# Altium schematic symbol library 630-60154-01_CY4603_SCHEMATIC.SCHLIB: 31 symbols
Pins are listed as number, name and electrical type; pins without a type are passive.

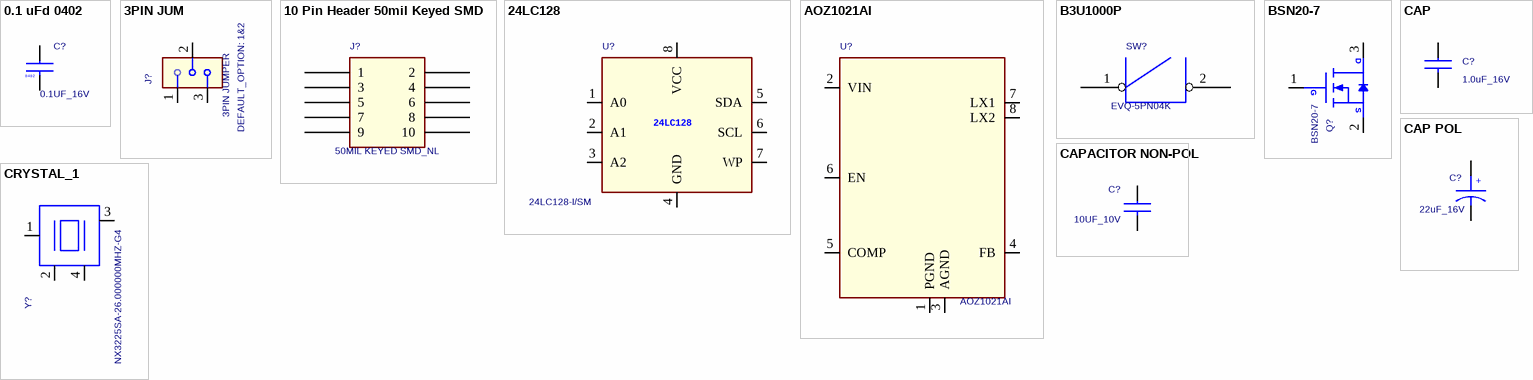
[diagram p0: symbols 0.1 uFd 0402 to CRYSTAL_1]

## 0.1 uFd 0402
designator C?, comment 0.1UF_16V
CAP .1UF 16V CERAMIC Y5V 0402; Cy_part#: 730R-10010; Manufacturer: Panasonic - ECG; Part Number: ECJ-0EF1C104Z; DEVICE: 0p1uFd_0402; CLASS: DISCRETE; ALT_SYMBOLS: C-CC0402_A
footprint CAPC1005X55M (Footprint not found)
footprint CC0402
pins: 1, 2

## 3PIN JUM
designator J?, comment 3PIN JUMPER  DEFAULT_OPTION: 1&2
CONN HEADER VERT 3POS .100 TIN; Part Number: 3-644456-3; Manufacturer: Tyco Electronics
footprint TE_3-644456-3 (Footprint not found)
pins: 1, 2, 3

## 10 Pin Header 50mil Keyed SMD
designator J?, comment 50MIL KEYED SMD_NL
CONN HEADER 10 PIN 50MIL KEYED SMD; Part Number: FTSH-105-01-L-DV-K; Manufacturer: Samtec; Cy_part#: 420R-14312; CLASS: IO; Last Edit By: SNF; DEVICE: HDR5x2x50KS
footprint SAMTEC_FTSH-105-01-L-DV-K (Footprint not found)
footprint ftsh-105-xx-x-dv-k
pins: 1, 2, 3, 4, 5, 6, 7, 8, 9, 10

## 24LC128
designator U?, comment 24LC128-I/SM
IC EEPROM 128KBIT 400KHZ 8SOIC; Manufacturer: Microchip Technology
footprint SOIC127P790X203-8M (Footprint not found)
footprint 8SOIC
pins: 1 A0, 2 A1, 3 A2, 4 GND, 5 SDA, 6 SCL, 7 WP, 8 VCC

## AOZ1021AI
designator U?
IC REG BUCK SYNC ADJ 3A 8SOIC; Manufacturer: Alpha & Omega Semiconductor Inc
footprint SOIC127P600X175-8M (Footprint not found)
footprint AOZ1021AI
pins: 1 PGND, 2 VIN, 3 AGND, 4 FB, 5 COMP, 6 EN, 7 LX1, 8 LX2

## B3U1000P
designator SW?, comment EVQ-5PN04K
footprint SW_EVQ-5PN04K (Footprint not found)
pins: 1, 2

## BSN20-7
designator Q?
MOSFET N-CH 50V 500MA SOT23; Manufacturer: Diodes Inc; PSpiceTemplate: X^@REFDES %D %G %S @MODEL
footprint SOT92P240X110-3M (Footprint not found)
pins: 1 G, 2 S, 3 D

## CAP
designator C?, comment 1.0uF_16V
CAP - CER, 1uF, 10V, +/-10%, X5R, 0402; Part Class: CAPACITORS; Num Pins: 2; Item Num: P03-15479R
footprint CAPC1608X90M (Footprint not found)
pins: 1, 2

## CAP POL
designator C?, comment 22uF_16V
CAP TANT 22UF 16V 10% 1206; Manufacturer: Nichicon; Part Number: F951C226KQAAQ2
footprint CAPCP3216X100M (Footprint not found)
pins: 1, 2

## CAPACITOR NON-POL
designator C?, comment 10UF_10V
footprint CAPC2012X145M (Footprint not found)
pins: 1, 2

## CRYSTAL_1
designator Y?, comment NX3225SA-26.000000MHZ-G4
Manufacturer: NDK
footprint OSCCC250X320X70-4M (Footprint not found)
pins: 1, 2, 3, 4

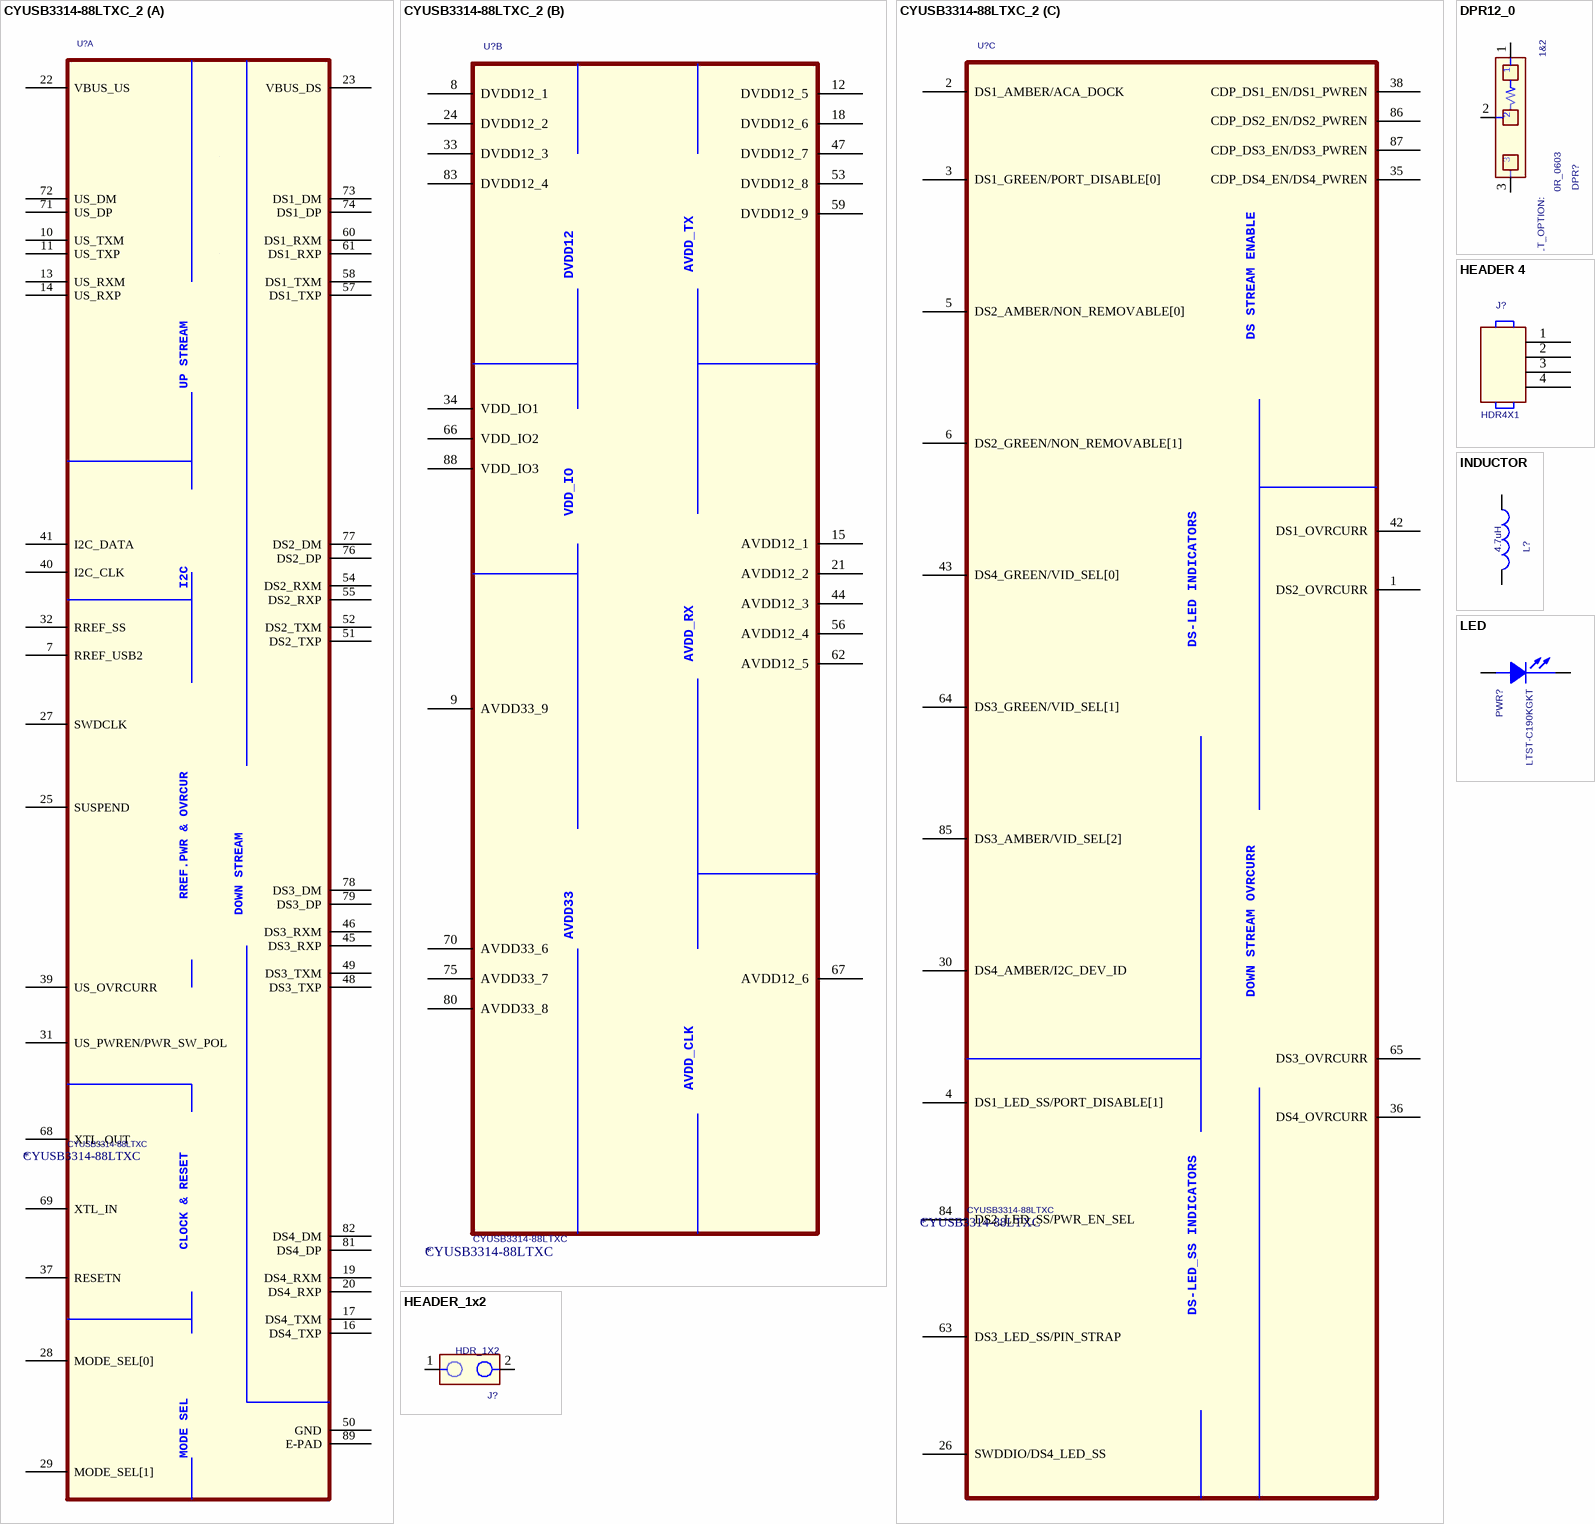
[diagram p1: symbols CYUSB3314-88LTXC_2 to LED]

## CYUSB3314-88LTXC_2
designator U?, comment CYUSB3314-88LTXC
footprint QFN40P1000X1000X100-89M (Footprint not found)
footprint QFN-88
part A pins: 7 RREF_USB2, 10 US_TXM, 11 US_TXP, 13 US_RXM, 14 US_RXP, 16 DS4_TXP, 17 DS4_TXM, 19 DS4_RXM, 20 DS4_RXP, 22 VBUS_US, 23 VBUS_DS, 25 SUSPEND, 27 SWDCLK, 28 MODE_SEL[0], 29 MODE_SEL[1], 31 US_PWREN/PWR_SW_POL, 32 RREF_SS, 37 RESETN, 39 US_OVRCURR, 40 I2C_CLK, 41 I2C_DATA, 45 DS3_RXP, 46 DS3_RXM, 48 DS3_TXP, 49 DS3_TXM, 50 GND, 51 DS2_TXP, 52 DS2_TXM, 54 DS2_RXM, 55 DS2_RXP, 57 DS1_TXP, 58 DS1_TXM, 60 DS1_RXM, 61 DS1_RXP, 68 XTL_OUT, 69 XTL_IN, 71 US_DP, 72 US_DM, 73 DS1_DM, 74 DS1_DP, 76 DS2_DP, 77 DS2_DM, 78 DS3_DM, 79 DS3_DP, 81 DS4_DP, 82 DS4_DM, 89 E-PAD
part B pins: 8 DVDD12_1, 9 AVDD33_9, 12 DVDD12_5, 15 AVDD12_1, 18 DVDD12_6, 21 AVDD12_2, 24 DVDD12_2, 33 DVDD12_3, 34 VDD_IO1, 44 AVDD12_3, 47 DVDD12_7, 53 DVDD12_8, 56 AVDD12_4, 59 DVDD12_9, 62 AVDD12_5, 66 VDD_IO2, 67 AVDD12_6, 70 AVDD33_6, 75 AVDD33_7, 80 AVDD33_8, 83 DVDD12_4, 88 VDD_IO3
part C pins: 1 DS2_OVRCURR, 2 DS1_AMBER/ACA_DOCK, 3 DS1_GREEN/PORT_DISABLE[0], 4 DS1_LED_SS/PORT_DISABLE[1], 5 DS2_AMBER/NON_REMOVABLE[0], 6 DS2_GREEN/NON_REMOVABLE[1], 26 SWDDIO/DS4_LED_SS, 30 DS4_AMBER/I2C_DEV_ID, 35 CDP_DS4_EN/DS4_PWREN, 36 DS4_OVRCURR, 38 CDP_DS1_EN/DS1_PWREN, 42 DS1_OVRCURR, 43 DS4_GREEN/VID_SEL[0], 63 DS3_LED_SS/PIN_STRAP, 64 DS3_GREEN/VID_SEL[1], 65 DS3_OVRCURR, 84 DS2_LED_SS/PWR_EN_SEL, 85 DS3_AMBER/VID_SEL[2], 86 CDP_DS2_EN/DS2_PWREN, 87 CDP_DS3_EN/DS3_PWREN

## DPR12_0
designator DPR?, comment 0R_0603  Mounting Status: 1&2
Resistor, 4.7K, 0402, 1/10W, 5%; Part Number: ERJ-2GEJ472X
footprint RC0603_3P (Footprint not found)
pins: 1, 2, 3
1 alternate drawing of the same symbol

## HEADER 4
designator J?, comment HDR4X1
CONN HEADER 4POS .100" SNGL GOLD; Manufacturer: Samtec Inc; Part Number: TSW-104-08-G-S
footprint SAMTEC_TSW-104-08-G-S (Footprint not found)
pins: 1, 2, 3, 4

## HEADER_1x2
designator J?, comment HDR_1X2
Manufacturer: Samtec Inc; Part Number: TSW-102-08-G-S
footprint SAMTEC_TSW-102-08-G-S (Footprint not found)
footprint HDR_1X2
pins: 1, 2

## INDUCTOR
designator L?, comment 4.7uH
INDUCTOR 4.7UH 2.7A 20% SMD; Part Number: NR6028T4R7M; Manufacturer: Taiyo Yuden
footprint IND_NR6028T4R7M (Footprint not found)
pins: 1, 2

## LED
designator PWR?, comment LTST-C190KGKT
LED GREEN CLEAR 0603 SMD; Manufacturer: Lite-On; Voltage Rating: 2V; CURRENT: 20mA
footprint LEDC1608X80M (Footprint not found)
pins: 1 ANODE, 2 CATHODE

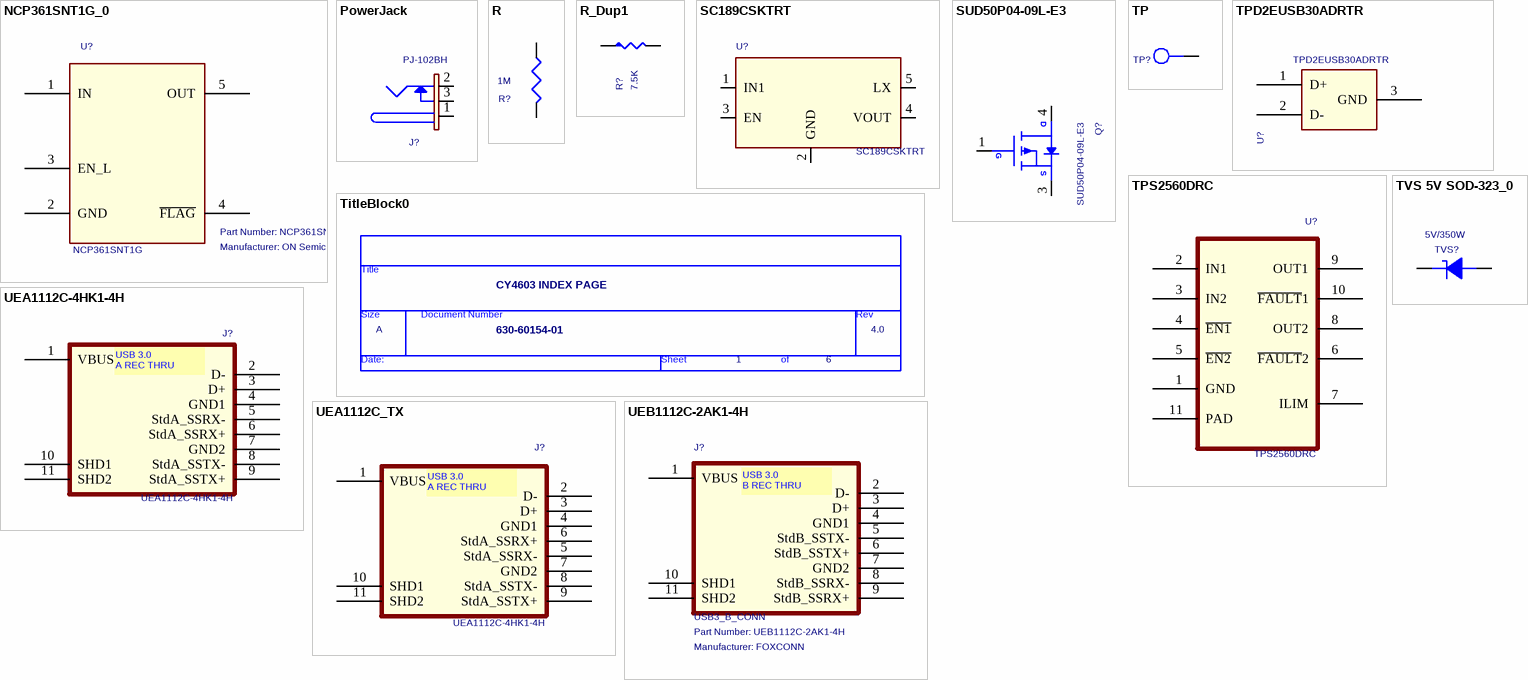
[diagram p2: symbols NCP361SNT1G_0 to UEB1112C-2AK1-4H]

## NCP361SNT1G_0
designator U?, comment NCP361SNT1G  Manufacturer: ON Semiconductor
IC USB POS OVP/OC_TSOP5
footprint SOP95P275X110-5M (Footprint not found)
footprint NCP361SNT1G_TSOP5
pins: 1 IN, 2 GND, 3 EN_L, 4 ~{FLAG}, 5 OUT

## PowerJack
designator J?, comment PJ-102BH
CONN PWR JACK 2.5X5.5MM HIGH CUR; Manufacturer: CUI Inc
footprint CUI_PJ-102BH (Footprint not found)
pins: 1, 2, 3

## R
designator R?, comment 1M
RES 1.00M OHM 1/10W 1% 0402 SMD; Manufacturer: Panasonic; Part Number: ERJ-2RKF1004X
footprint RESC1005X40M (Footprint not found)
pins: 1, 2

## R_Dup1
designator R?, comment 7.5K
RES 7.5K OHM 1/10W 1% 0603 SMD; Part Number: ERJ-3EKF7501V; Manufacturer: Panasonic - ECG
footprint RESC1608X55M (Footprint not found)
footprint RC0603
pins: 1, 2

## SC189CSKTRT
designator U?
IC REG BUCK SYNC 1.2V SOT23-5; Manufacturer: Semtech
footprint SOT95P280X145-5M (Footprint not found)
footprint SC189CSKTRT
pins: 1 IN1, 2 GND, 3 EN, 4 VOUT, 5 LX

## SUD50P04-09L-E3
designator Q?
footprint TO228P991X238-3M (Footprint not found)
pins: 1 G, 3 S, 4 D

## TitleBlock0
designator *?  Page Count: 6  Page Number: 1  Page Size: A  Title: CY4603 INDEX PAGE  RevCode: 4.0  Doc: 630-60154-01  (hidden comment: TitleBlock0)  (graphical)

## TP
designator TP?, comment TP_RED  (value not drawn)
TEST POINT PC MINI .040"D RED; Manufacturer: Keystone; Part Number: 5000
footprint KEYSTONE_5000 (Footprint not found)
pins: 1 TP

## TPD2EUSB30ADRTR
designator U?
footprint SOTFL35P100X50-3M (Footprint not found)
footprint SOTFL35P100X50-3M (Footprint not found)
pins: 1 D+, 2 D-, 3 GND

## TPS2560DRC
designator U?
footprint SON50P300X300X100-11M (Footprint not found)
footprint SON-10
pins: 1 GND, 2 IN1, 3 IN2, 4 ~{EN1}, 5 ~{EN2}, 6 ~{FAULT}2, 7 ILIM, 8 OUT2, 9 OUT1, 10 ~{FAULT}1, 11 PAD

## TVS 5V SOD-323_0
designator TVS?, comment 5V/350W
TVS UNIDIR 350W 5V SOD-323; Part Number: SD05.TCT; Manufacturer: Dioded Inc.; CLASS: DISCRETE; DEVICE: SD05-7; LastEditBy: gir
footprint SOD2513X120M (Footprint not found)
footprint SOD323
pins: 1 K, 2 A

## UEA1112C-4HK1-4H
designator J?
9 Position Right Angle 3.0 USB Connector; Manufacturer: FOXCONN
footprint FOXCONN_UEA1112C-4HK1-4H (Footprint not found)
pins: 1 VBUS, 2 D-, 3 D+, 4 GND1, 5 StdA_SSRX-, 6 StdA_SSRX+, 7 GND2, 8 StdA_SSTX-, 9 StdA_SSTX+, 10 SHD1, 11 SHD2

## UEA1112C_TX
designator J?, comment UEA1112C-4HK1-4H
9 Position Right Angle 3.0 USB Connector; Manufacturer: FOXCONN
footprint FOXCONN_UEA1112C-4HK1-4H (Footprint not found)
pins: 1 VBUS, 2 D-, 3 D+, 4 GND1, 5 StdA_SSRX-, 6 StdA_SSRX+, 7 GND2, 8 StdA_SSTX-, 9 StdA_SSTX+, 10 SHD1, 11 SHD2

## UEB1112C-2AK1-4H
designator J?, comment USB3_B_CONN  Manufacturer: FOXCONN  Part Number: UEB1112C-2AK1-4H
USB 3.0 B Series Right Angle,T/H 9 Pos
footprint FOXCONN_UEB1112C-2AK1-4H (Footprint not found)
footprint UEB1112C-2AK1-4H
pins: 1 VBUS, 2 D-, 3 D+, 4 GND1, 5 StdB_SSTX-, 6 StdB_SSTX+, 7 GND2, 8 StdB_SSRX-, 9 StdB_SSRX+, 10 SHD1, 11 SHD2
